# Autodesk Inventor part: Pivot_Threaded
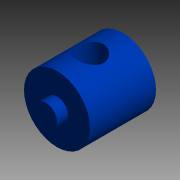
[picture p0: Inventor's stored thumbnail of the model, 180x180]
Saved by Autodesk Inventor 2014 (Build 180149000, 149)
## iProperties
Shininess: 0.0
Length Units: 11272
Angle Units: 11279
Time Units: 11290
Mass Units: 11283
Length Display Precision: 2
Angle Display Precision: 1
Compacted: True
Created: 1999-05
Part Number: Pivot_Threaded
Document SubType Name: Modeling
Designer: Administrator
Density: 7.85 g/cm^3
Material: Steel
Mass: 37.2426 g
Surface Area: 21.7773 cm^2
Volume: 4.74428 cm^3
Appearance: Blue - Semi Gloss
Density: 0.0
Volumn: 0.0
Area: 0.0
PropertySet Name: Model Information
Control State: 0
Master: False
Checked Out: False
Author: Administrator
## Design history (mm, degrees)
node "y-z Plane"
  node "x-z Plane"
  node "x-y Plane"
node "Extrusion1" dims "d1" = 19.05, "d2" = 0
  sketch "Sketch1"
    geometry: C1 r 9.525 at (0, 0); 1 further point
    constraints: 1 centre point, 1 coincident
    dimensions: "d0" = 19.05 diameter of C1
node "Extrusion2" dims "d3" = 3.175, "d4" = 0
  sketch "Sketch2"
    geometry: C1 r 9.525 at (0, 0) reference; C2 r 3.175 at (0, 0)
    constraints: 1 centre point
    dimensions: "d18" = 6.35 diameter of C2
node "Extrusion3" dims "d6" = 3.175, "d7" = 0
  sketch "Sketch3"
    geometry: C1 r 9.525 at (0, 0) reference; C2 r 3.175 at (0, 0)
    constraints: 1 centre point
    dimensions: "d5" = 6.35 diameter of C2
workplane "Work Plane1"
  workaxis "Work Axis1"
workplane "Work Plane2"
node "Hole1" dims "d12" = 7.7978, "d13" = 9.525, "d14" = 6.35, "d15" = 60 deg, "d16" = 19.05, "d17" = 118 deg
  sketch "Sketch4"
    geometry: 2 further points
    constraints: 1 coincident
node "Sketch5"
node "Sketch6"
workaxis "Work Axis2"
body "Solid1"
other parameters: "d8" = 0, "d9" = 9.525
